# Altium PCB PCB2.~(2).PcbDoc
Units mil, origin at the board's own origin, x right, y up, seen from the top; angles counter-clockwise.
Board outline 1968 x 1968 mil, 4 copper layers (Top Layer, Internal Plane 1, Internal Plane 2, Bottom Layer), stack 18.2 mil thick; 11 components, 11 nets, 36 pads, 0 vias.
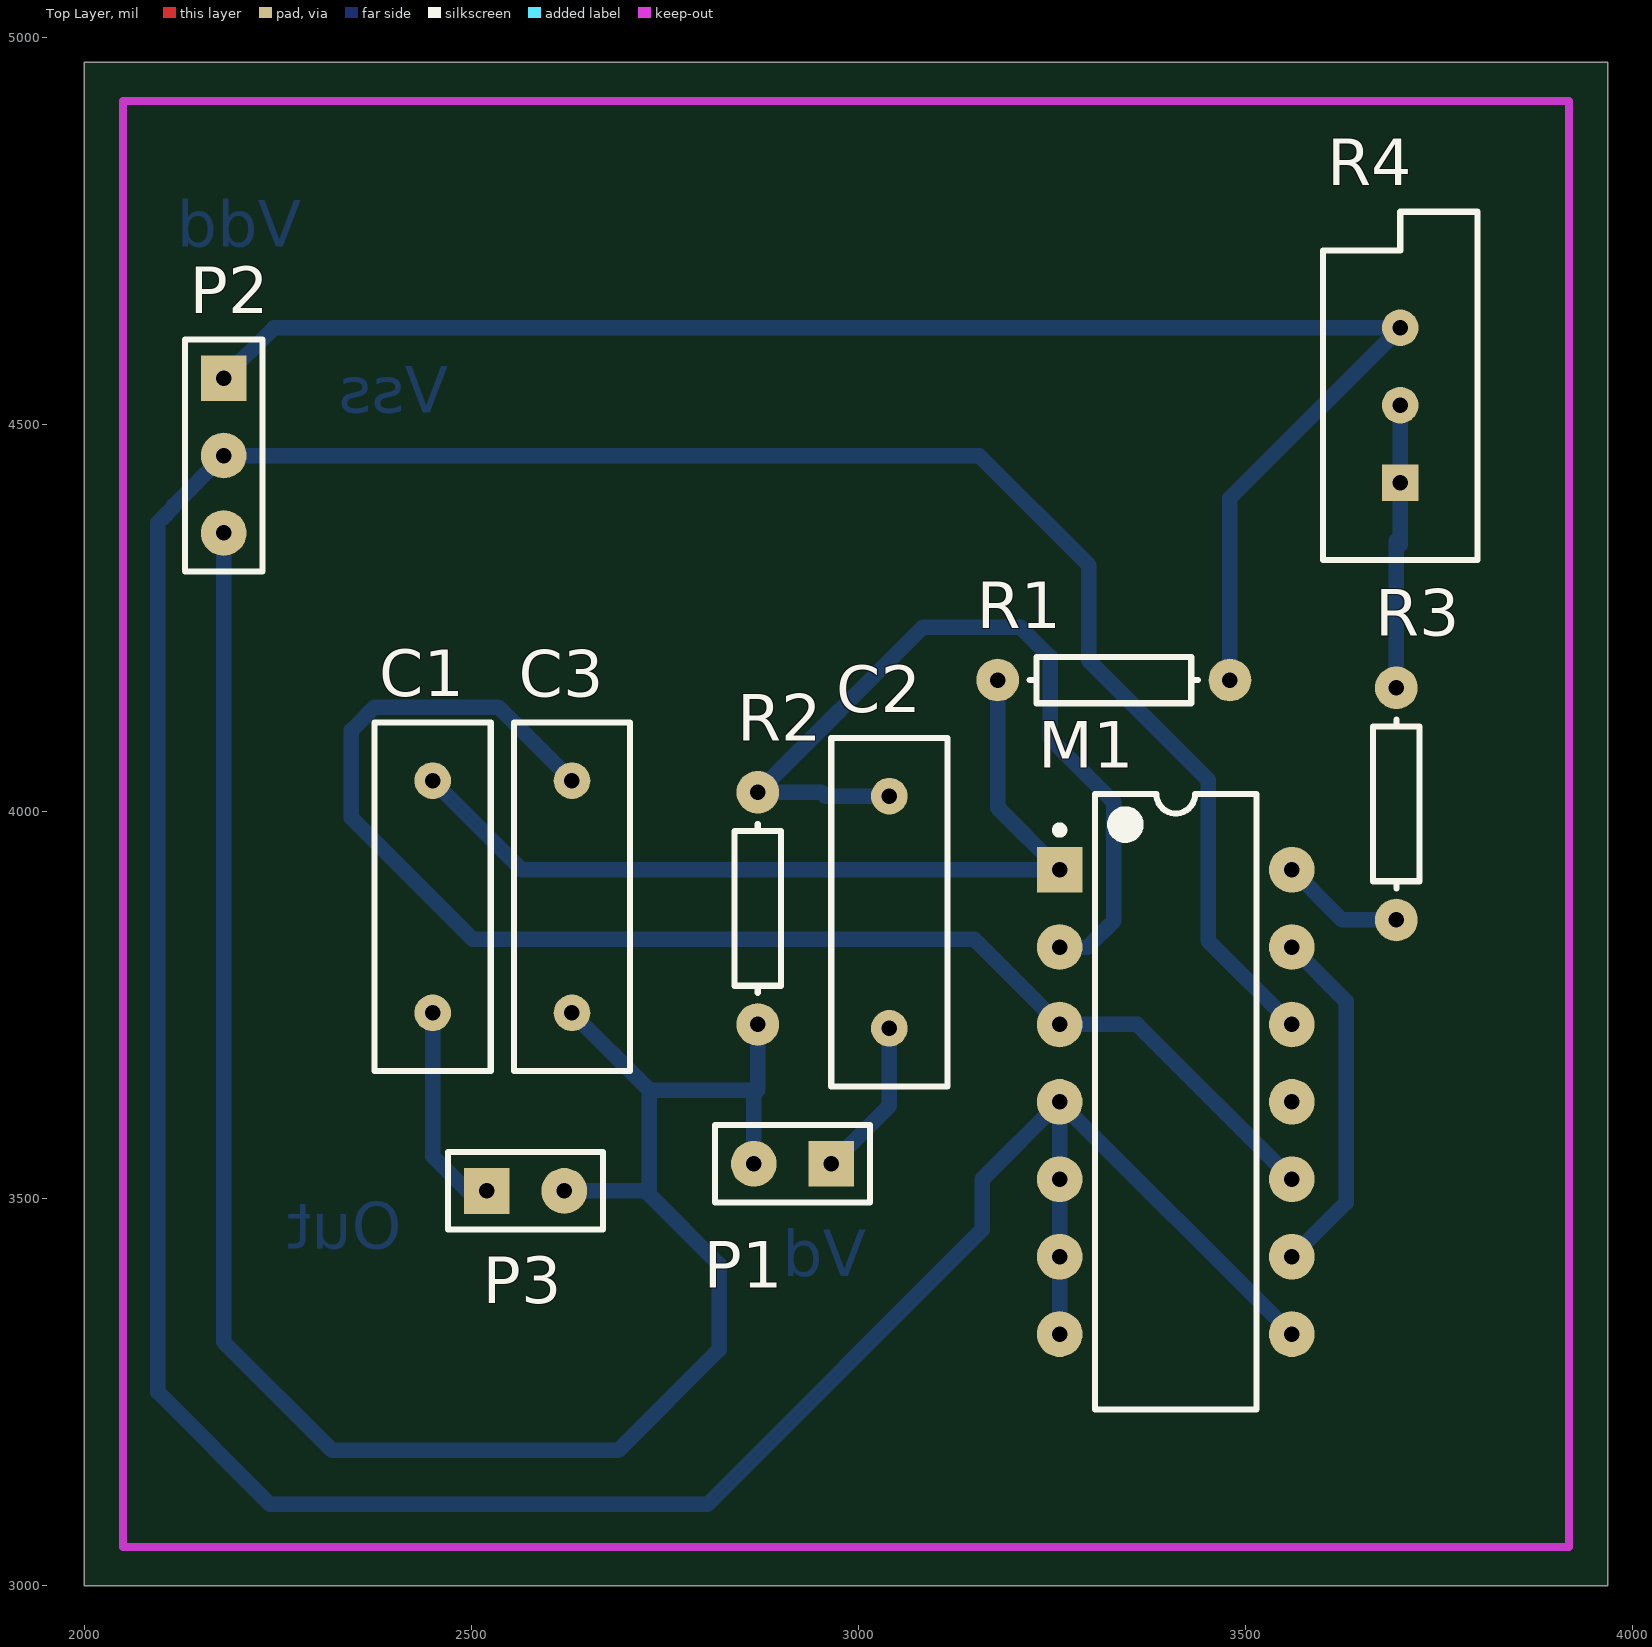
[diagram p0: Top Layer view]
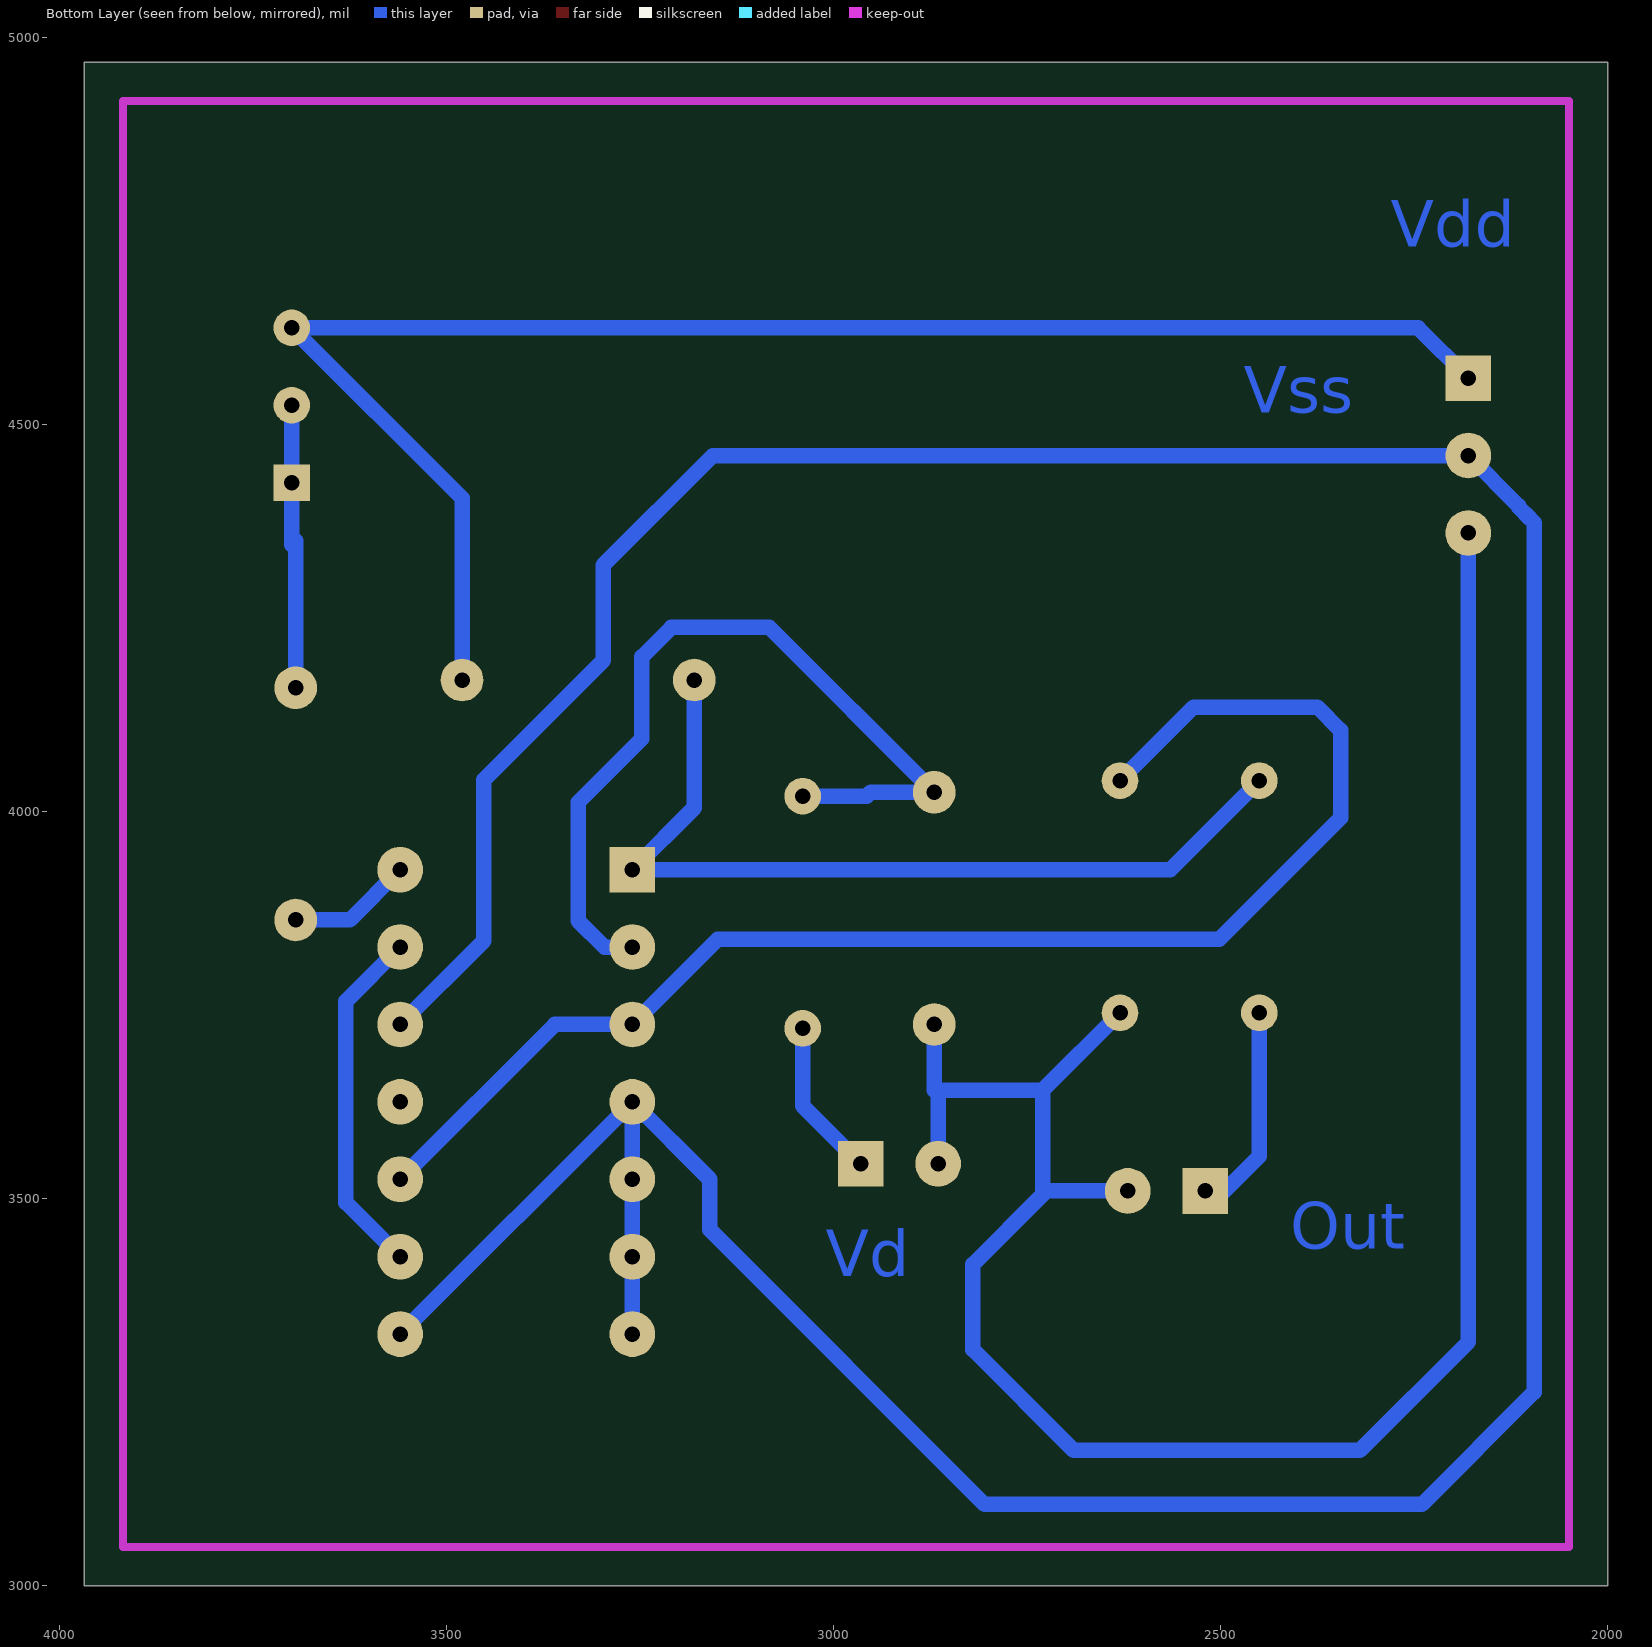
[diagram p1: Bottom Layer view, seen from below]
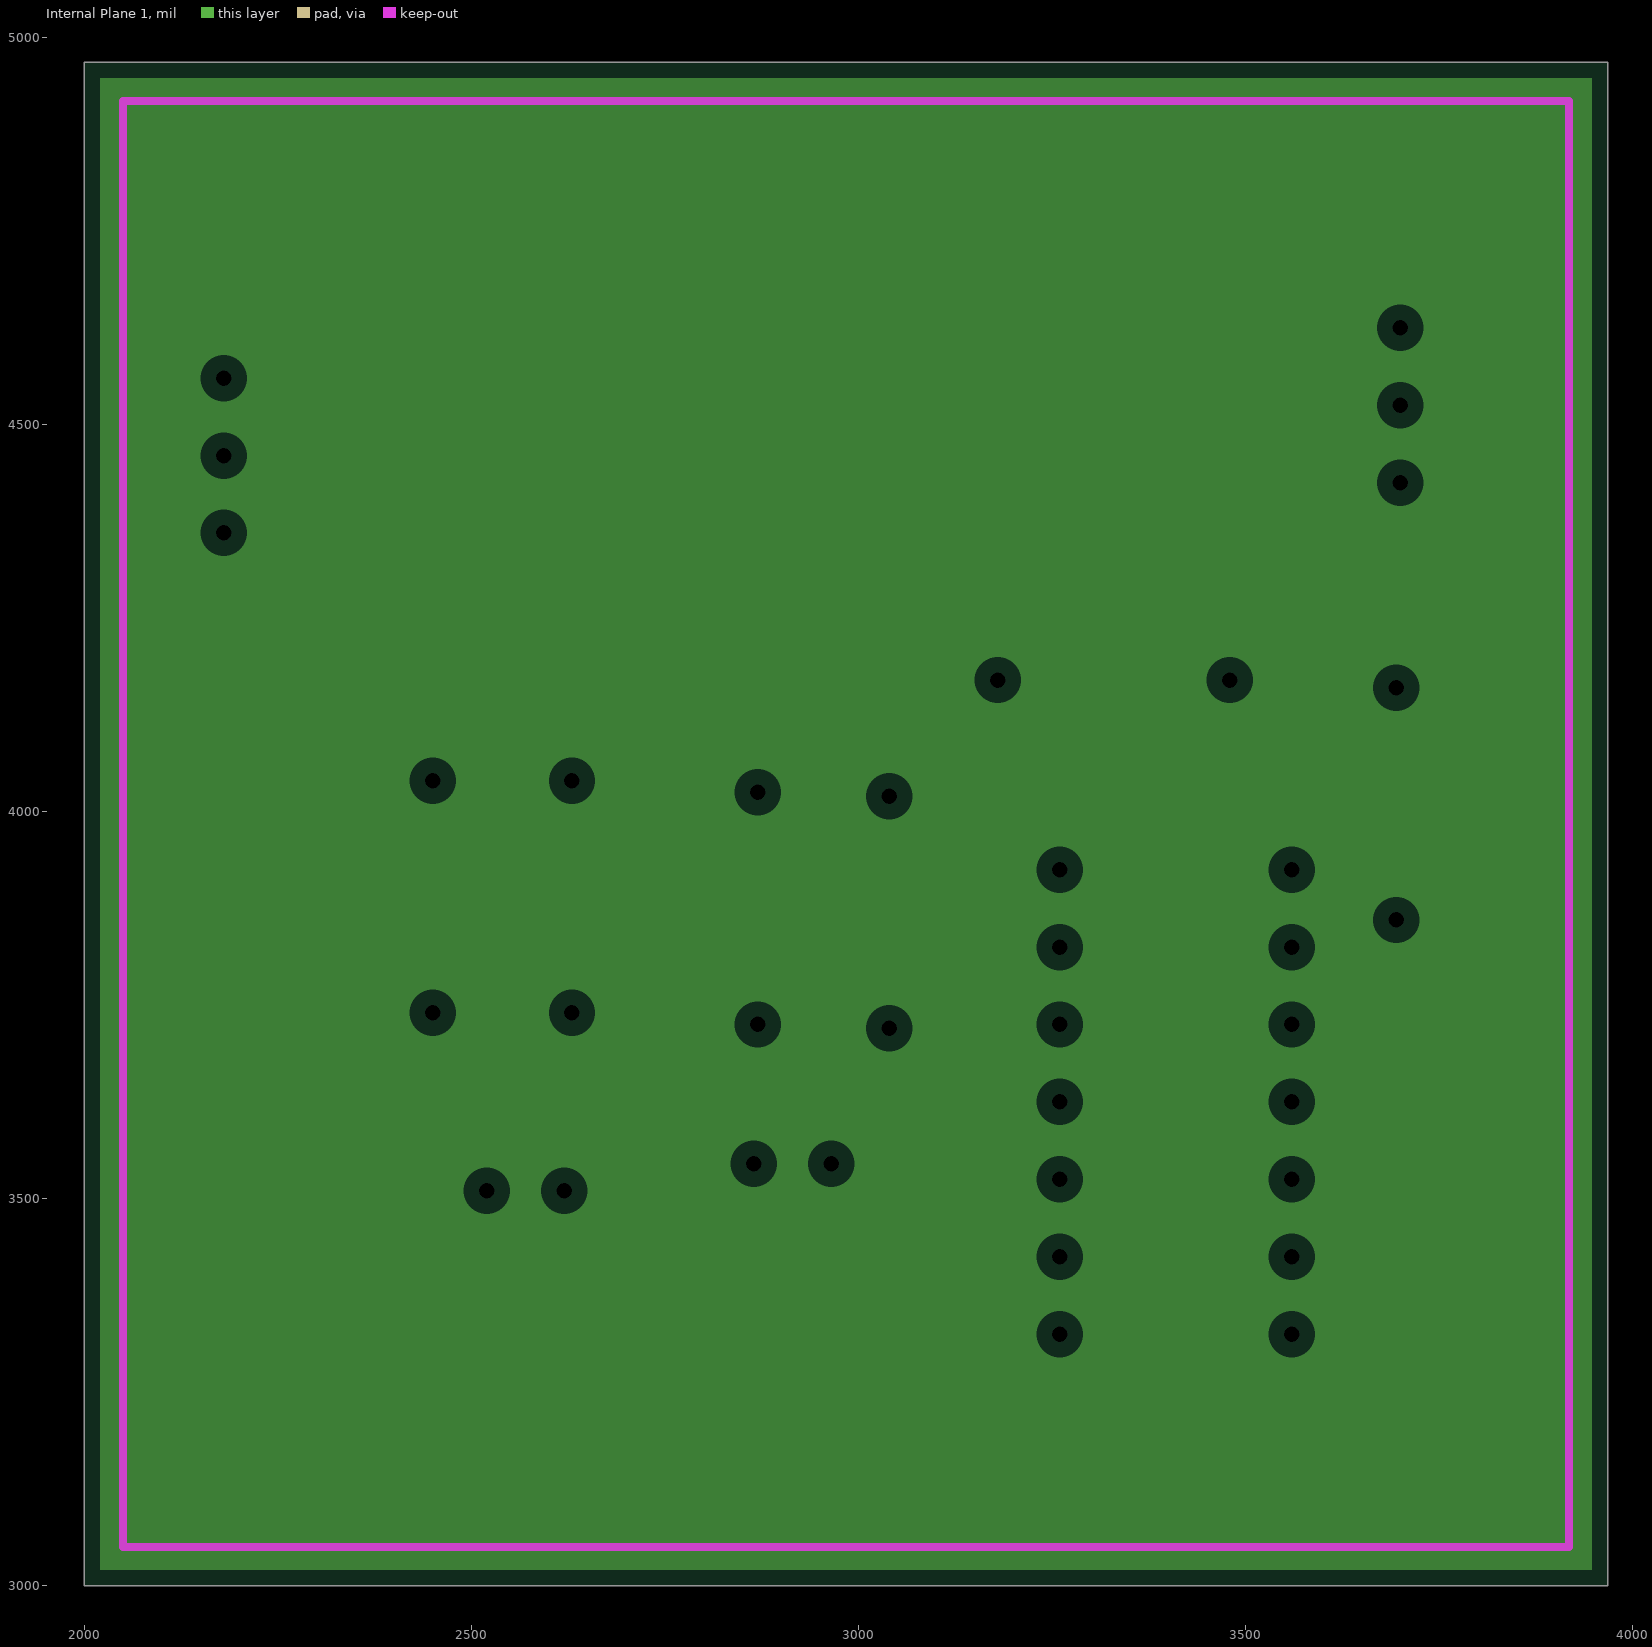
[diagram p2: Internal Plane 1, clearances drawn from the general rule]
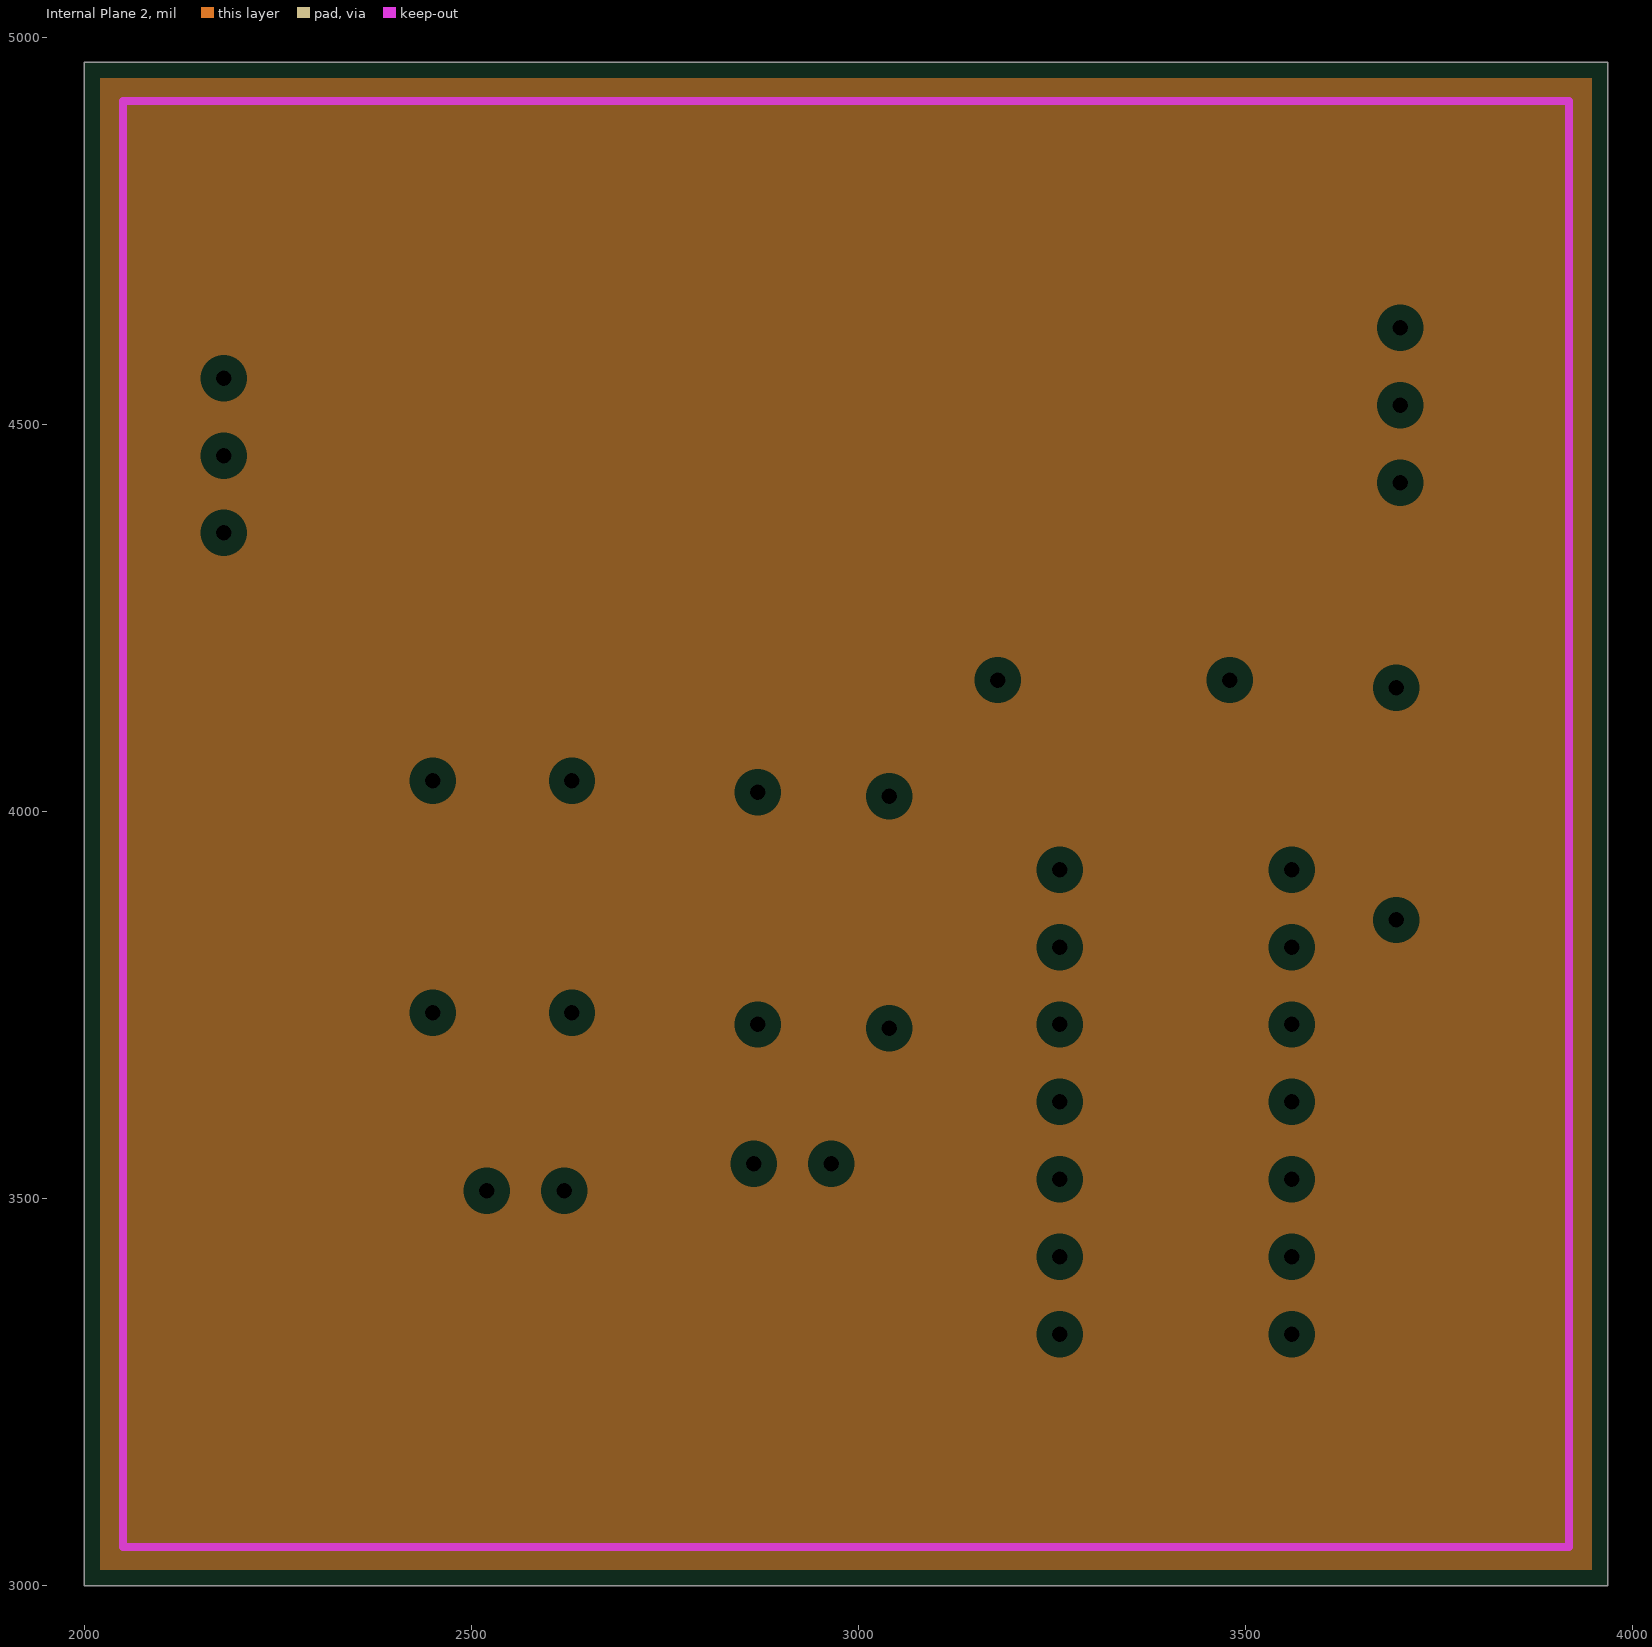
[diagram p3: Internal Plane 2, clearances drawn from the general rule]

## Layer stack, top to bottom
Top Solder: solder mask 0.4, Solder Resist, Dk 3.5
Top Layer: signal copper 1.4
Internal Plane 1: plane copper 1.4
Internal Plane 2: plane copper 1.4
Dielectric 1: dielectric 12.6, FR-4, Dk 4.8
Bottom Layer: signal copper 1.4
Bottom Solder: solder mask 0.4, Solder Resist, Dk 3.5

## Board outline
2000,3000 3968,3000 3968,4968 2000,4968

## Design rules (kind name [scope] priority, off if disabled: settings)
Clearance [All] p1: gap=30
PlaneClearance [All] p1: clearance=20
PlaneConnect [All] p1: planeconnectstyle=Relief reliefexpansion=20 reliefentries=4 reliefconductorwidth=10 reliefairgap=10
PolygonConnect [All] p1: connectstyle=Relief reliefconductorwidth=10 reliefentries=4 polygonreliefangle="90 Angle" airgapwidth=10
RoutingVias [All] p1: holewidth=32 width=62 viastyle="Through Hole" minholewidth=28 minwidth=50 maxholewidth=28 maxwidth=50
SolderMaskExpansion [All] p1: expansion=4
Width [All] p1: maxlimit=20 minlimit=20 preferedwidth=20
28 further rules are at their usual default settings.

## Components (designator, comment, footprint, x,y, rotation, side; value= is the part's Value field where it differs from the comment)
C1 "C3" RAD-0.3 2450,3890 r270 top
C2 "C2" RAD-0.3 3040,3870 r90 top
C3 "C1" RAD-0.3 2630,3890 r90 top
M1 "ALD1106" DIP-14 3410,3625 r0 top
P1 "Header 2" HDR1X2 2965,3545 r180 top
P2 "Header 3" HDR1X3 2180,4560 r270 top
P3 "Header 2" HDR1X2 2520,3510 r0 top
R1 "RD" AXIAL-0.3 3330,4170 r0 top
R2 "Res1" AXIAL-0.3 2870,3875 r90 top
R3 "Res1" AXIAL-0.3 3695,4010 r90 top
R4 "RPot" VR5 3700,4525 r90 top

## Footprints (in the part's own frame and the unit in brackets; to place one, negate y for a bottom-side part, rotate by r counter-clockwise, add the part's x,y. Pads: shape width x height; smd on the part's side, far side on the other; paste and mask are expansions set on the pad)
AXIAL-0.3 [mm] "Axial Device, Thru-Hole; 2 Leads; 0.3 in Pin Spacing"
  round 1.4 hole 0.508: 1(-3.81,0) 2(3.81,0)
  silkscreen extent -2.77,-0.76 2.77,0.76
DIP-14 [mm] "DIP, 14-Pin, Row Spacing 7.62 mm, Pitch 2.54 mm"
  rect 1.5x1.5 hole 0.508: 1(-3.81,7.62)
  round 1.5 hole 0.508: 2(-3.81,5.08) 3(-3.81,2.54) 4(-3.81,0) 5(-3.81,-2.54) 6(-3.81,-5.08) 7(-3.81,-7.62) 8(3.81,-7.62) 9(3.81,-5.08) 10(3.81,-2.54) 11(3.81,0) 12(3.81,2.54) 13(3.81,5.08) 14(3.81,7.62)
  silkscreen extent -3.93,-10.1 2.65,10.1, body extent -3.6,-10.1 3.6,10.1, height 5.08
HDR1X2 [mm] "Connector; Header; 2 Position"
  rect 1.5x1.5 hole 0.508: 1(0,0)
  round 1.5 hole 0.508: 2(2.54,0)
  silkscreen extent -1.27,-1.27 3.81,1.27
HDR1X3 [mm] "Connector; Header; 3 Position"
  rect 1.5x1.5 hole 0.508: 1(0,0)
  round 1.5 hole 0.508: 2(2.54,0) 3(5.08,0)
  silkscreen extent -1.27,-1.27 6.35,1.27
RAD-0.3 [mm] "Radial Cap, Thru-Hole; 2 Leads; 0.3 in Pin Spacing"
  round 1.2 hole 0.508: 1(-3.81,0) 2(3.81,0)
  silkscreen extent -5.71,-1.91 5.71,1.91
VR5 [mm] "Thru-Hole; 3 Leads"
  rect 1.2x1.2 hole 0.508: 1(-2.54,0)
  round 1.2 hole 0.508: 2(0,0) 3(2.54,0)
  silkscreen extent -5.08,-2.54 6.35,2.54

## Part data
C1 C2 C3: library part Cap, "Capacitor"
M1: "Quad N-channel matched MOSFET array"
P1 P3: "Header, 2-Pin"
P2: "Header, 3-Pin"
R1: library part Res1, "Resistor"
R2 R3: "Resistor"
R4: "Potentiometer"

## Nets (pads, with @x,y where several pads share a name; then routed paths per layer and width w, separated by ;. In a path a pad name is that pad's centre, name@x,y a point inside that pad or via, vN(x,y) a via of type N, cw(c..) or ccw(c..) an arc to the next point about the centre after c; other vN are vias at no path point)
GND: C3.1 P1.2 P2.3 P3.2 R2.1 | length 2714.5
  Bottom Layer w20: P2.3 2180,3315 2320,3175 2690,3175 2820,3305 2820,3415 2730,3505 2730,3640 ; P3.2 2725,3510 ; C3.1 2730,3640 ; 2857,3640 2730,3640 ; P1.2 2865,3632 ; 2870,3640 R2.1
NetC1_1: C1.1 M1.1 R1.1 | length 1135.8
  Bottom Layer w20: C1.1 2565,3925 M1.1 3180,4005 R1.1
NetC1_2: C1.2 P3.1 | length 252.2
  Bottom Layer w20: C1.2 2450,3555 P3.1@2497.5,3507.5
NetC2_1: C2.1 P1.1 | length 206.1
  Bottom Layer w20: P1.1 3040,3620 C2.1
NetC2_2: C2.2 M1.2 R2.2 | length 1112.8
  Bottom Layer w20: C2.2 2957,4020 2952,4025 R2.2 3083,4238 3209.56,4238 3247.56,4200 3247.56,4094.44 3330,4012 3330,3859 3296,3825 M1.2
NetC3_2: C3.2 M1.3 M1.10 | length 1858.2
  Bottom Layer w20: C3.2 2535,4135 2375,4135 2345,4105 2345,3992 2502,3835 3150,3835 M1.3 3360,3725 M1.10
NetM1_4: M1.4 M1.5 M1.6 M1.7 M1.8 M1.12 P2.2 | length 5347.6
  Bottom Layer w20: 2100,4378.33 2115,4393.33 ; M1.7 M1.6 M1.5 M1.4 ; M1.8 M1.4 ; M1.12 3452,3833 3452,4041 3297.56,4195.44 3297.56,4318.45 3156.01,4460 P2.2 2179.16,4459.16 2115,4395 2115,4393.33 ; 2115,4393.33 2095,4373.33 2095,3250 2240,3105 2805,3105 3160,3460 3160,3525 M1.4
NetM1_9: M1.9 M1.13 | length 458
  Bottom Layer w20: M1.9 3630,3495 3630,3755 M1.13
NetM1_14: M1.14 R3.1 | length 161.9
  Bottom Layer w20: M1.14 3625,3860 R3.1
NetP2_1: P2.1 R1.2 R4.3 | length 2093.1
  Bottom Layer w20: P2.1 2245,4625 R4.3 3480,4405 R1.2
NetR3_2: R3.2 R4.1 R4.2 | length 377.1
  Bottom Layer w20: R3.2 3695,4350 3700,4345 R4.1 R4.2
pads on no net: M1.11

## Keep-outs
Keep-Out Layer:
  lines w10: 2050,3050 3918,3050 3918,4918 2050,4918 2050,3050

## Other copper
Bottom Layer:
  text "Vdd" at 2280,4730 h60
  text "Vss" at 2470,4515 h60
  text "Out" at 2410,3435 h60
  text "Vd" at 3010,3400 h60

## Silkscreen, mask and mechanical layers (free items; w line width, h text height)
Drill Drawing:
  text ".LEGEND" at 1058,1840 h60
  text "Drill Drawing." at 1058,1740 h60

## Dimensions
2050,3050 to 3918,3050 on Mechanical 1
2050,3050 to 2050,4918 on Mechanical 1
